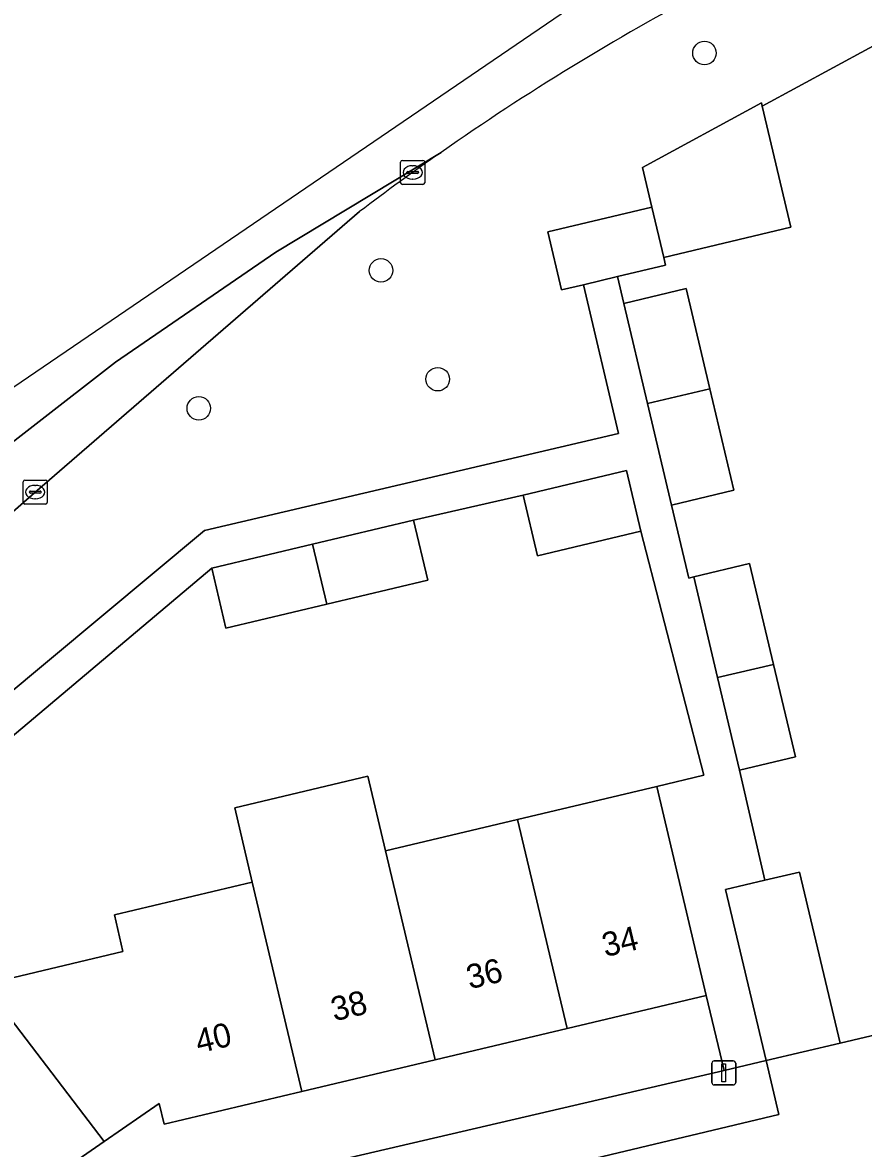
# Model space of a CAD drawing. Extents: x 158031 to 159244, y 380104 to 381214.
# Drawn here: x 158378.95 to 158413.91, y 381055.07 to 381101.88 of the extents above; entities that cross this region are included whole.
import ezdxf

# ---------------------------------------------------------------- set-up
doc = ezdxf.new("R2010")
doc.units = 0
for name, color, linetype in [('IMGEO_Berm_groen', 7, 'Continuous'), ('IMGEO_Boom', 7, 'Continuous'), ('IMGEO_Erf', 7, 'Continuous'), ('IMGEO_Kolk', 7, 'Continuous'), ('IMGEO_Lichtmast', 7, 'Continuous'), ('IMGEO_Muur', 7, 'Continuous'), ('IMGEO_Pand', 7, 'Continuous'), ('IMGEO_Pand_nummerreeks', 7, 'Continuous'), ('IMGEO_Parkeervlak_open', 7, 'Continuous'), ('IMGEO_Rijbaan_regionaal_gesloten', 7, 'Continuous'), ('IMGEO_Voetpad_open', 7, 'Continuous')]:
    doc.layers.add(name, color=color, linetype=linetype)

msp = doc.modelspace()

# ---------------------------------------------------------------- linework, layer by layer
at = {"layer": 'IMGEO_Berm_groen'}
for points in [[(158360.887, 381059.398), (158386.519, 381080.758), (158403.729, 381084.79), (158402.268, 381090.979), (158401.355, 381090.763), (158400.783, 381093.174), (158405.113, 381094.199), (158404.723, 381095.843), (158409.674, 381098.532), (158409.705, 381098.402), (158417.108, 381102.413), (158419.965, 381103.129), (158419.788, 381103.877), (158426.532, 381105.474), (158426.688, 381104.815), (158433.978, 381106.643), (158434.68, 381108.792), (158437.722, 381109.577), (158437.546, 381110.54), (158456.233, 381114.875)], [(158392.967, 381094.018), (158379.556, 381082.426), (158338.208, 381046.187)]]:
    msp.add_lwpolyline(points, dxfattribs=at)
for centre, radius, start, end in [((158457.951, 381008.241), 107.613, 118.00355, 124.92001), ((158457.357, 381009.025), 106.63, 124.89948, 127.14721)]:
    msp.add_arc(centre, radius, start, end, dxfattribs=at)
at = {"layer": 'IMGEO_Boom'}
for centre in [(158407.3, 381100.607), (158393.854, 381091.572), (158396.213, 381087.048), (158386.279, 381085.839)]:
    msp.add_circle(centre, 0.489, dxfattribs=at)
at = {"layer": 'IMGEO_Erf'}
for points in [[(158417.108, 381102.413), (158409.705, 381098.402), (158410.897, 381093.368), (158405.607, 381092.115), (158405.684, 381091.788), (158403.681, 381091.314), (158403.944, 381090.201), (158406.535, 381090.815), (158407.522, 381086.646), (158408.521, 381082.431), (158405.929, 381081.817), (158406.65, 381078.785), (158406.854, 381078.833), (158409.174, 381079.385), (158410.17, 381075.196), (158411.084, 381071.354), (158408.763, 381070.802), (158409.81, 381066.22), (158411.257, 381066.563), (158412.941, 381059.452), (158422.017, 381061.593)], [(158377.361, 381061.894), (158383.128, 381063.259), (158382.768, 381064.778), (158388.504, 381066.136), (158387.771, 381069.23), (158393.313, 381070.544), (158394.047, 381067.449), (158399.533, 381068.749), (158405.319, 381070.119), (158407.277, 381070.583), (158404.658, 381080.729), (158400.358, 381079.711), (158399.761, 381082.232), (158395.204, 381081.184), (158395.795, 381078.691), (158391.602, 381077.698), (158387.409, 381076.704), (158386.818, 381079.198), (158361.921, 381058.214)], [(158374.512, 381038.654), (158383.116, 381052.496), (158387.343, 381053.48), (158408.115, 381058.316), (158407.378, 381061.428), (158401.593, 381060.058), (158396.107, 381058.758), (158390.564, 381057.445), (158384.834, 381056.088), (158384.63, 381056.947), (158382.344, 381055.362), (158379.776, 381053.581), (158380.582, 381053.083), (158377.309, 381047.779)]]:
    msp.add_lwpolyline(points, dxfattribs=at)
at = {"layer": 'IMGEO_Kolk'}
for p, q in [((158394.671, 381095.217), (158394.671, 381096.069)), ((158394.746, 381096.143), (158395.598, 381096.143)), ((158395.159, 381095.923), (158395.184, 381095.923)), ((158395.672, 381096.069), (158395.672, 381095.217)), ((158394.93, 381095.637), (158394.93, 381095.649)), ((158395.368, 381095.6), (158394.97, 381095.6)), ((158394.973, 381095.686), (158395.371, 381095.686)), ((158395.182, 381095.363), (158395.157, 381095.363)), ((158395.414, 381095.649), (158395.414, 381095.637)), ((158395.598, 381095.143), (158394.746, 381095.143)), ((158378.979, 381081.93), (158378.979, 381082.782)), ((158379.054, 381082.856), (158379.906, 381082.856)), ((158379.98, 381082.782), (158379.98, 381081.93)), ((158379.238, 381082.35), (158379.238, 381082.362)), ((158379.676, 381082.313), (158379.278, 381082.313)), ((158379.281, 381082.399), (158379.679, 381082.399)), ((158379.467, 381082.636), (158379.492, 381082.636)), ((158379.722, 381082.362), (158379.722, 381082.35)), ((158379.906, 381081.856), (158379.054, 381081.856)), ((158379.49, 381082.076), (158379.465, 381082.076))]:
    msp.add_line(p, q, dxfattribs=at)
for points in [[(158394.671, 381095.217), (158394.671, 381096.069)], [(158394.746, 381096.143), (158395.598, 381096.143)], [(158395.672, 381096.069), (158395.672, 381095.217)], [(158395.598, 381095.143), (158394.746, 381095.143)], [(158378.979, 381081.93), (158378.979, 381082.782)], [(158379.054, 381082.856), (158379.906, 381082.856)], [(158379.98, 381082.782), (158379.98, 381081.93)], [(158379.906, 381081.856), (158379.054, 381081.856)]]:
    msp.add_lwpolyline(points, dxfattribs=at)
for centre, radius, start, end in [((158394.748, 381096.067), 0.0765, 91.552, 178.448), ((158394.748, 381096.067), 0.0765, 91.552, 178.448), ((158395.596, 381096.067), 0.0765, 1.552, 88.448), ((158395.596, 381096.067), 0.0765, 1.552, 88.448), ((158394.97, 381095.646), 0.0403, 85.8775, 175.7526), ((158394.967, 381095.636), 0.0366, 178.938, 274.7102), ((158395.371, 381095.643), 0.043, 264.8664, 352.4533), ((158395.375, 381095.648), 0.0386, 1.7309, 96.639), ((158394.748, 381095.219), 0.0765, 181.552, 268.448), ((158394.748, 381095.219), 0.0765, 181.552, 268.448), ((158395.596, 381095.219), 0.0765, 271.552, 358.448), ((158395.596, 381095.219), 0.0765, 271.552, 358.448), ((158379.056, 381082.78), 0.0765, 91.552, 178.448), ((158379.056, 381082.78), 0.0765, 91.552, 178.448), ((158379.904, 381082.78), 0.0765, 1.552, 88.448), ((158379.904, 381082.78), 0.0765, 1.552, 88.448), ((158379.278, 381082.359), 0.0403, 85.8775, 175.7526), ((158379.275, 381082.349), 0.0366, 178.938, 274.7102), ((158379.679, 381082.356), 0.043, 264.8664, 352.4533), ((158379.683, 381082.361), 0.0386, 1.7309, 96.639), ((158379.056, 381081.932), 0.0765, 181.552, 268.448), ((158379.056, 381081.932), 0.0765, 181.552, 268.448), ((158379.904, 381081.932), 0.0765, 271.552, 358.448), ((158379.904, 381081.932), 0.0765, 271.552, 358.448)]:
    msp.add_arc(centre, radius, start, end, dxfattribs=at)
for centre, major_axis, ratio, start_param, end_param in [((158395.158, 381095.643), (-0.387, 0.002), 0.722429, 4.712389, 7.853982), ((158395.183, 381095.643), (-0.39, 0.002), 0.717154, 1.570796, 4.712389), ((158379.466, 381082.356), (-0.387, 0.002), 0.722429, 4.712389, 7.853982), ((158379.491, 381082.356), (-0.39, 0.002), 0.717154, 1.570796, 4.712389)]:
    msp.add_ellipse(centre, major_axis=major_axis, ratio=ratio, start_param=start_param, end_param=end_param, dxfattribs=at)
at = {"layer": 'IMGEO_Lichtmast'}
for p, q in [((158407.609, 381057.811), (158407.609, 381058.611)), ((158407.609, 381058.611), (158407.609, 381057.811)), ((158407.709, 381058.711), (158408.499, 381058.711)), ((158408.499, 381058.711), (158407.709, 381058.711)), ((158408.599, 381058.611), (158408.599, 381057.811)), ((158408.599, 381057.811), (158408.599, 381058.611)), ((158408.499, 381057.711), (158407.709, 381057.711)), ((158407.709, 381057.711), (158408.499, 381057.711))]:
    msp.add_line(p, q, dxfattribs=at)
msp.add_lwpolyline([(158408.029, 381058.586), (158408.179, 381058.586), (158408.179, 381057.836), (158408.029, 381057.836), (158408.029, 381058.586)], dxfattribs=at)
for centre, start, end in [((158407.709, 381058.611), 90, 180), ((158407.709, 381058.611), 90, 180), ((158408.499, 381058.611), 0, 90), ((158408.499, 381058.611), 360, 90), ((158407.709, 381057.811), 180, 270), ((158407.709, 381057.811), 180, 270), ((158408.499, 381057.811), 270, 0), ((158408.499, 381057.811), 270, 0)]:
    msp.add_arc(centre, 0.1, start, end, dxfattribs=at)
at = {"layer": 'IMGEO_Muur'}
msp.add_lwpolyline([(158412.941, 381059.452), (158422.017, 381061.593), (158421.283, 381064.763), (158423.191, 381065.209)], dxfattribs=at)
at = {"layer": 'IMGEO_Pand'}
for points in [[(158409.705, 381098.402), (158409.674, 381098.532), (158404.723, 381095.843), (158405.113, 381094.199), (158405.607, 381092.115), (158410.897, 381093.368)], [(158405.113, 381094.199), (158400.783, 381093.174), (158401.355, 381090.763), (158402.268, 381090.979), (158403.681, 381091.314), (158405.684, 381091.788), (158405.607, 381092.115)], [(158404.931, 381086.033), (158407.522, 381086.646), (158406.535, 381090.815), (158403.944, 381090.201)], [(158404.931, 381086.033), (158405.929, 381081.817), (158408.521, 381082.431), (158407.522, 381086.646)], [(158400.358, 381079.711), (158404.658, 381080.729), (158404.061, 381083.251), (158399.761, 381082.232)], [(158391.007, 381080.19), (158391.602, 381077.698), (158395.795, 381078.691), (158395.204, 381081.184)], [(158391.007, 381080.19), (158386.818, 381079.198), (158387.409, 381076.704), (158391.602, 381077.698)], [(158409.174, 381079.385), (158406.854, 381078.833), (158407.849, 381074.646), (158410.17, 381075.196)], [(158410.17, 381075.196), (158407.849, 381074.646), (158408.763, 381070.802), (158411.084, 381071.354)], [(158388.504, 381066.136), (158390.564, 381057.445), (158396.107, 381058.758), (158394.047, 381067.449), (158393.313, 381070.544), (158387.771, 381069.23)], [(158399.533, 381068.749), (158401.593, 381060.058), (158407.378, 381061.428), (158405.319, 381070.119)], [(158394.047, 381067.449), (158396.107, 381058.758), (158401.593, 381060.058), (158399.533, 381068.749)], [(158411.257, 381066.563), (158409.81, 381066.22), (158408.18, 381065.834), (158409.864, 381058.723), (158412.941, 381059.452)], [(158377.361, 381061.894), (158382.344, 381055.362), (158384.63, 381056.947), (158384.834, 381056.088), (158390.564, 381057.445), (158388.504, 381066.136), (158382.768, 381064.778), (158383.128, 381063.259)], [(158377.361, 381061.894), (158376.033, 381059.743), (158372.572, 381061.88), (158367.574, 381053.784), (158369.66, 381052.497), (158377.309, 381047.779), (158380.582, 381053.083), (158379.776, 381053.581), (158382.344, 381055.362)]]:
    msp.add_lwpolyline(points, close=True, dxfattribs=at)
at = {"layer": 'IMGEO_Parkeervlak_open'}
msp.add_lwpolyline([(158409.864, 381058.723), (158408.115, 381058.316), (158387.343, 381053.48), (158387.886, 381051.146), (158402.78, 381054.674), (158410.396, 381056.477)], close=True, dxfattribs=at)
at = {"layer": 'IMGEO_Rijbaan_regionaal_gesloten'}
for points in [[(158477.712, 381133.114), (158427.759, 381117.397), (158425.671, 381116.489), (158421.878, 381114.755), (158418.148, 381112.891), (158414.666, 381111.189), (158413.825, 381110.745), (158361.695, 381075.218)], [(158361.695, 381075.218), (158361.289, 381074.859), (158359.75, 381073.529), (158356.699, 381070.839), (158355.197, 381069.515), (158353.694, 381068.217), (158352.07, 381066.802), (158349.039, 381064.162), (158346.03, 381061.497), (158342.958, 381058.812), (158338.453, 381054.873), (158336.948, 381053.503), (158333.889, 381050.808), (158330.831, 381048.113), (158329.303, 381046.767), (158327.801, 381045.444), (158325.399, 381043.328), (158327.79, 381040.547), (158373.028, 381080.17), (158382.823, 381087.764), (158389.479, 381092.337), (158396.35, 381096.478)], [(158396.35, 381096.478), (158389.479, 381092.337), (158382.823, 381087.764), (158373.028, 381080.17), (158327.79, 381040.547), (158329.502, 381038.556), (158338.208, 381046.187), (158379.556, 381082.426)], [(158379.556, 381082.426), (158392.967, 381094.018)]]:
    msp.add_lwpolyline(points, dxfattribs=at)
for centre, radius, start, end in [((158457.951, 381008.241), 107.613, 118.00355, 124.92001), ((158457.357, 381009.025), 106.63, 124.89948, 127.14721)]:
    msp.add_arc(centre, radius, start, end, dxfattribs=at)
at = {"layer": 'IMGEO_Voetpad_open'}
for points in [[(158456.233, 381114.875), (158437.546, 381110.54), (158437.722, 381109.577), (158434.68, 381108.792), (158433.978, 381106.643), (158435.275, 381092.725), (158433.608, 381092.249), (158434.781, 381086.992), (158433.567, 381086.7), (158436.161, 381075.363), (158434.986, 381075.07), (158435.62, 381065.721), (158433.532, 381065.232), (158434.119, 381062.705), (158422.391, 381059.979), (158422.017, 381061.593), (158412.941, 381059.452), (158409.864, 381058.723), (158410.396, 381056.477), (158402.78, 381054.674), (158387.886, 381051.146), (158387.343, 381053.48), (158383.116, 381052.496), (158374.512, 381038.654)], [(158361.921, 381058.214), (158386.818, 381079.198), (158391.007, 381080.19), (158395.204, 381081.184), (158399.761, 381082.232), (158404.061, 381083.251), (158404.658, 381080.729), (158407.277, 381070.583), (158405.319, 381070.119), (158407.378, 381061.428), (158408.115, 381058.316), (158409.864, 381058.723), (158408.18, 381065.834), (158409.81, 381066.22), (158408.763, 381070.802), (158407.849, 381074.646), (158406.854, 381078.833), (158406.65, 381078.785), (158405.929, 381081.817), (158404.931, 381086.033), (158403.944, 381090.201), (158403.681, 381091.314), (158402.268, 381090.979), (158403.729, 381084.79), (158386.519, 381080.758), (158360.887, 381059.398)]]:
    msp.add_lwpolyline(points, dxfattribs=at)

# ---------------------------------------------------------------- texts
at = {"layer": 'IMGEO_Pand_nummerreeks'}
for s, p in [('34', (158403.176, 381063.022)), ('36', (158397.54, 381061.687)), ('38', (158391.907, 381060.352)), ('40', (158386.271, 381059.017))]:
    msp.add_text(s, height=1, rotation=13.3261, dxfattribs=at).set_placement(p)

doc.saveas('drawing.dxf')
